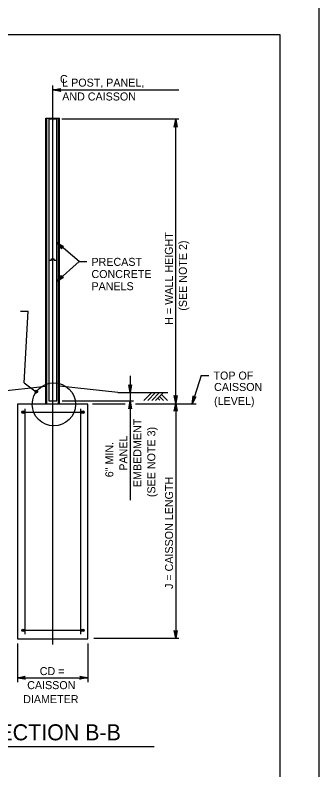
# Model space of a CAD drawing. Extents: x 3475 to 6558, y -3780 to 1166.
# Drawn here: x 4485.7 to 4602.3, y 274.7 to 564.2 of the extents above; entities that cross this region are included whole.
import ezdxf

# ---------------------------------------------------------------- set-up
doc = ezdxf.new("R2010")
doc.units = 0
for name, color, linetype in [('1', 7, 'Continuous'), ('2', 7, 'Continuous'), ('PLT-BNDY', 7, 'Continuous')]:
    doc.layers.add(name, color=color, linetype=linetype)

msp = doc.modelspace()

# ---------------------------------------------------------------- linework, layer by layer
at = {"layer": '1'}
for p, q in [((4500.22, 322.83), (4500.22, 537.23)), ((4500.22, 535.48), (4548.62, 535.48)), ((4497.5, 524.6), (4502.76, 524.6)), ((4497.5, 415.02), (4497.5, 524.6)), ((4497.88, 415.02), (4497.88, 524.6)), ((4502.38, 415.02), (4502.38, 524.6)), ((4502.76, 415.02), (4502.76, 524.6)), ((4503.6, 524.45), (4548.52, 524.45)), ((4547.39, 415.27), (4547.39, 524.22)), ((4500.37, 523.94), (4500.24, 523.77)), ((4498.73, 488.22), (4498.72, 488.22)), ((4498.72, 488.22), (4498.72, 470.22)), ((4501.72, 470.22), (4501.72, 488.95)), ((4510.35, 469.72), (4501.72, 476.93)), ((4498.72, 470.22), (4498.72, 452.47)), ((4499.74, 470.22), (4499.74, 470.7)), ((4499.74, 470.7), (4500.7, 470.7)), ((4500.7, 470.22), (4500.7, 470.7)), ((4501.72, 452.78), (4501.72, 470.22)), ((4510.35, 469.72), (4501.72, 461.97)), ((4510.35, 469.72), (4513.25, 469.72)), ((4487.84, 450.58), (4490.74, 450.58)), ((4489.2, 423.13), (4490.74, 450.58)), ((4529.89, 425.81), (4529.89, 378.18)), ((4557.14, 425.97), (4553.65, 415.14)), ((4557.14, 425.97), (4560.04, 425.97)), ((4489.2, 423.13), (4493.87, 419.76)), ((4475.09, 419.45), (4497.5, 421.81)), ((4525.17, 419.45), (4502.76, 421.81)), ((4525.17, 419.45), (4544.37, 419.45)), ((4535.16, 416.43), (4538.16, 419.43)), ((4536.66, 416.43), (4539.66, 419.43)), ((4538.16, 416.43), (4541.16, 419.43)), ((4539.66, 416.43), (4542.66, 419.43)), ((4541.34, 416.49), (4540.51, 417.31)), ((4542.66, 416.43), (4541.16, 417.93)), ((4544.16, 416.43), (4541.91, 418.68)), ((4513.59, 415.02), (4486.59, 415.02)), ((4486.59, 415.02), (4486.59, 325.02)), ((4503.79, 416.22), (4531.22, 416.22)), ((4513.59, 325.02), (4513.59, 415.02)), ((4515.47, 415.14), (4527.97, 415.14)), ((4531.94, 415.14), (4555.19, 415.14)), ((4547.39, 415.27), (4547.39, 325.16)), ((4488.39, 411.92), (4511.73, 411.92)), ((4489.54, 326.81), (4489.54, 413.2)), ((4510.9, 326.81), (4510.9, 413.14)), ((4488.39, 328.24), (4511.73, 328.24)), ((4486.59, 325.02), (4513.59, 325.02)), ((4515.89, 325.17), (4548.52, 325.17)), ((4486.59, 323.2), (4486.59, 308.39)), ((4513.59, 323.2), (4513.59, 308.39)), ((4486.59, 310.03), (4513.59, 310.03)), ((4473.79, 283.67), (4539.09, 283.67))]:
    msp.add_line(p, q, dxfattribs=at)
for points in [[(4500.22, 535.48), (4503.2, 536.04), (4502.97, 535.88), (4502.85, 535.68), (4502.82, 535.48), (4502.85, 535.28), (4502.97, 535.08), (4503.2, 534.92), (4500.22, 535.48), (4502.97, 535.08), (4502.85, 535.28), (4500.22, 535.48), (4502.82, 535.48), (4502.85, 535.68), (4500.22, 535.48), (4502.97, 535.88)], [(4501.72, 506.53), (4501.72, 524.22), (4498.72, 524.22), (4498.72, 505.74)], [(4547.39, 524.22), (4547.95, 521.24), (4547.79, 521.47), (4547.59, 521.59), (4547.39, 521.62), (4547.19, 521.59), (4546.99, 521.47), (4546.83, 521.24), (4547.39, 524.22), (4546.99, 521.47), (4547.19, 521.59), (4547.39, 524.22), (4547.39, 521.62), (4547.59, 521.59), (4547.39, 524.22), (4547.79, 521.47)], [(4501.72, 488.51), (4501.72, 506.8)], [(4498.72, 506.05), (4498.72, 488.22)], [(4501.72, 476.93), (4504.36, 475.44), (4504.09, 475.47), (4503.87, 475.39), (4503.71, 475.26), (4503.61, 475.08), (4503.57, 474.86), (4503.65, 474.59), (4501.72, 476.93), (4503.57, 474.86), (4503.61, 475.08), (4501.72, 476.93), (4503.71, 475.26), (4503.87, 475.39), (4501.72, 476.93), (4504.09, 475.47)], [(4498.72, 470.22), (4499.74, 470.22)], [(4500.7, 470.22), (4501.72, 470.22)], [(4501.72, 461.97), (4503.56, 464.38), (4503.5, 464.11), (4503.54, 463.88), (4503.65, 463.71), (4503.81, 463.59), (4504.03, 463.52), (4504.31, 463.55), (4501.72, 461.97), (4504.03, 463.52), (4503.81, 463.59), (4501.72, 461.97), (4503.65, 463.71), (4503.54, 463.88), (4501.72, 461.97), (4503.5, 464.11)], [(4498.72, 453.23), (4498.72, 434.49)], [(4501.72, 434.46), (4501.72, 453.16)], [(4498.72, 416.22), (4501.72, 416.22), (4501.72, 435)], [(4498.72, 434.7), (4498.72, 416.22)], [(4529.89, 419.45), (4529.33, 422.44), (4529.49, 422.21), (4529.69, 422.09), (4529.89, 422.05), (4530.09, 422.09), (4530.29, 422.21), (4530.45, 422.44), (4529.89, 419.45), (4530.29, 422.21), (4530.09, 422.09), (4529.89, 419.45), (4529.89, 422.05), (4529.69, 422.09), (4529.89, 419.45), (4529.49, 422.21)], [(4547.39, 415.27), (4546.83, 418.25), (4546.99, 418.02), (4547.19, 417.9), (4547.39, 417.87), (4547.59, 417.9), (4547.79, 418.02), (4547.95, 418.25), (4547.39, 415.27), (4547.79, 418.02), (4547.59, 417.9), (4547.39, 415.27), (4547.39, 417.87), (4547.19, 417.9), (4547.39, 415.27), (4546.99, 418.02)], [(4553.65, 415.14), (4554.03, 418.15), (4554.11, 417.88), (4554.26, 417.71), (4554.44, 417.61), (4554.65, 417.59), (4554.87, 417.64), (4555.09, 417.81), (4553.65, 415.14), (4554.87, 417.64), (4554.65, 417.59), (4553.65, 415.14), (4554.44, 417.61), (4554.26, 417.71), (4553.65, 415.14), (4554.11, 417.88)], [(4529.89, 416.22), (4530.45, 413.24), (4530.29, 413.47), (4530.09, 413.59), (4529.89, 413.62), (4529.69, 413.59), (4529.49, 413.47), (4529.33, 413.24), (4529.89, 416.22), (4529.49, 413.47), (4529.69, 413.59), (4529.89, 416.22), (4529.89, 413.62), (4530.09, 413.59), (4529.89, 416.22), (4530.29, 413.47)], [(4547.39, 415.27), (4547.95, 412.28), (4547.79, 412.51), (4547.59, 412.63), (4547.39, 412.67), (4547.19, 412.63), (4546.99, 412.51), (4546.83, 412.28), (4547.39, 415.27), (4546.99, 412.51), (4547.19, 412.63), (4547.39, 415.27), (4547.39, 412.67), (4547.59, 412.63), (4547.39, 415.27), (4547.79, 412.51)], [(4547.39, 325.16), (4546.83, 328.15), (4546.99, 327.92), (4547.19, 327.8), (4547.39, 327.76), (4547.59, 327.8), (4547.79, 327.92), (4547.95, 328.15), (4547.39, 325.16), (4547.79, 327.92), (4547.59, 327.8), (4547.39, 325.16), (4547.39, 327.76), (4547.19, 327.8), (4547.39, 325.16), (4546.99, 327.92)], [(4486.59, 310.03), (4489.57, 310.59), (4489.34, 310.43), (4489.23, 310.23), (4489.19, 310.03), (4489.23, 309.83), (4489.34, 309.63), (4489.57, 309.47), (4486.59, 310.03), (4489.34, 309.63), (4489.23, 309.83), (4486.59, 310.03), (4489.19, 310.03), (4489.23, 310.23), (4486.59, 310.03), (4489.34, 310.43)], [(4513.59, 310.03), (4510.61, 309.47), (4510.84, 309.63), (4510.96, 309.83), (4510.99, 310.03), (4510.96, 310.23), (4510.84, 310.43), (4510.61, 310.59), (4513.59, 310.03), (4510.84, 310.43), (4510.96, 310.23), (4513.59, 310.03), (4510.99, 310.03), (4510.96, 309.83), (4513.59, 310.03), (4510.84, 309.63)]]:
    msp.add_lwpolyline(points, dxfattribs=at)
for centre, radius in [((4500.6, 414.9), 8.3), ((4493.87, 419.76), 0.533), ((4493.87, 419.76), 0.267), ((4488.74, 411.91), 0.468), ((4488.74, 411.91), 0.354), ((4488.74, 411.91), 0.253), ((4488.74, 411.91), 0.143), ((4511.73, 411.91), 0.468), ((4511.73, 411.91), 0.354), ((4511.73, 411.91), 0.253), ((4511.73, 411.91), 0.143), ((4488.74, 328.26), 0.468), ((4488.74, 328.26), 0.354), ((4488.74, 328.26), 0.253), ((4488.74, 328.26), 0.143), ((4511.73, 328.23), 0.468), ((4511.73, 328.23), 0.354), ((4511.73, 328.23), 0.253), ((4511.73, 328.23), 0.143)]:
    msp.add_circle(centre, radius, dxfattribs=at)
at = {"layer": '2'}
for p, q in [((3801.34, 556.69), (4587.34, 556.69)), ((4587.34, 556.69), (4587.34, -7.31))]:
    msp.add_line(p, q, dxfattribs=at)
at = {"layer": 'PLT-BNDY'}
msp.add_lwpolyline([(3761.34, 571.69), (4602.34, 571.69), (4602.34, -22.31), (3761.34, -22.31)], close=True, dxfattribs=at)

# ---------------------------------------------------------------- texts
at = {"layer": '1'}
for s, height, p in [('C', 3.07, (4502.94, 538.14)), ('L POST, PANEL,', 3.0721, (4503.81, 536.75)), ('AND CAISSON', 3.0721, (4503.81, 531.44)), ('PRECAST', 3.072, (4515.03, 468.01)), ('CONCRETE', 3.072, (4515.03, 463.34)), ('PANELS', 3.072, (4515.03, 458.67)), ('TOP OF', 3.072, (4561.88, 424.4)), ('CAISSON', 3.072, (4562.1, 420.03)), ('(LEVEL)', 3.072, (4562.1, 414.66)), ('CD =', 3.072, (4495.18, 311.04)), ('CAISSON', 3.072, (4490.37, 305.67)), ('DIAMETER', 3.072, (4488.83, 300.29)), ('SECTION B-B', 6.1441, (4473.83, 286.04))]:
    msp.add_text(s, height=height, dxfattribs=at).set_placement(p)
for s, height, p in [('H = WALL HEIGHT', 3.0721, (4546.29, 445.42)), ('(SEE NOTE 2)', 3.0721, (4551.66, 450.81)), ('EMBEDMENT', 3.072, (4534.18, 383.16)), ('(SEE NOTE 3)', 3.0721, (4539.55, 379.32)), ('PANEL', 3.072, (4528.8, 389.45)), ('6" MIN.', 3.072, (4523.42, 386.93)), ('J = CAISSON LENGTH', 3.0721, (4546.34, 344.07))]:
    msp.add_text(s, height=height, rotation=90, dxfattribs=at).set_placement(p)

doc.saveas('drawing.dxf')
